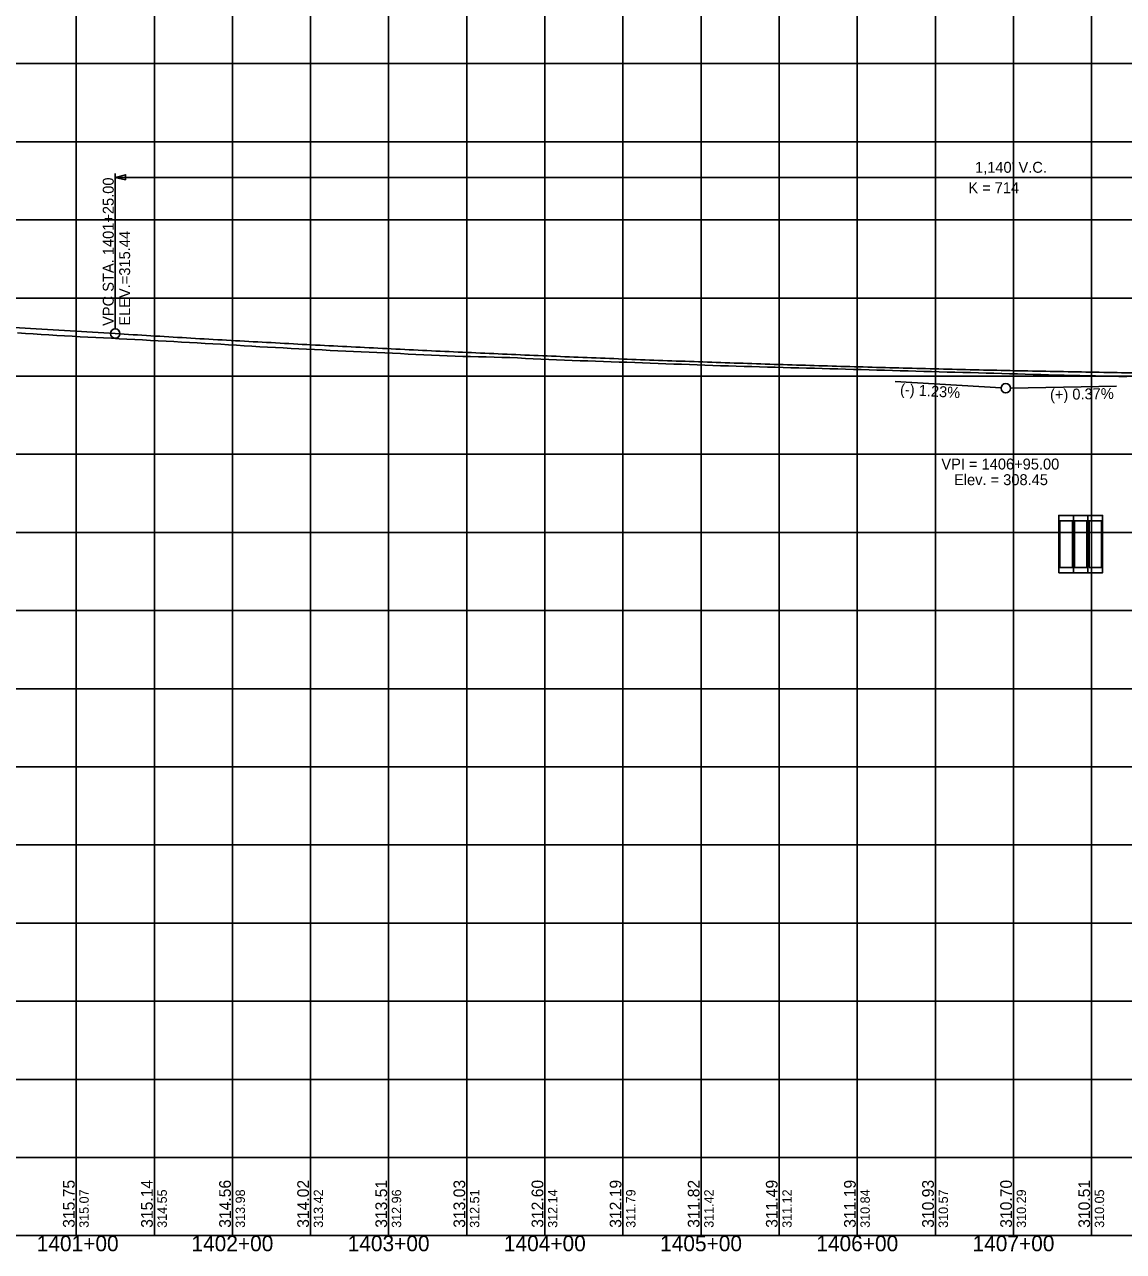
# Model space of a CAD drawing. Extents: x -90830 to 2015517, y -20856 to 836331.
# Drawn here: x 28990 to 29694, y -10807 to -10022 of the extents above; entities that cross this region are included whole.
import ezdxf

# ---------------------------------------------------------------- set-up
doc = ezdxf.new("R2010")
doc.units = 0
for name, color, linetype in [('Level 1', 7, 'Continuous'), ('RD_DDB_GradeTX', 7, 'Continuous'), ('RD_DDB_Profile_Elev', 7, 'Continuous'), ('RD_DDB_Profile_EX', 7, 'Continuous'), ('RD_DDB_Profile_Lbl', 7, 'Continuous'), ('RD_DDB_Profile_PR', 7, 'Continuous'), ('RD_DDB_StaTX', 7, 'Continuous'), ('RD_DDB_StripGrade', 7, 'Continuous'), ('RD_DDB_VCLbl', 7, 'Continuous'), ('RD_EX_DR_Pipe', 7, 'Continuous'), ('RD_GPK_Profile_Cell', 7, 'Continuous'), ('RD_TX_Drainage', 7, 'Continuous')]:
    doc.layers.add(name, color=color, linetype=linetype)

msp = doc.modelspace()

# ---------------------------------------------------------------- linework, layer by layer
at = {"layer": 'Level 1'}
for p, q in [((29023.46, -9797.12), (29023.46, -10297.12)), ((29073.46, -9797.12), (29073.46, -10297.12)), ((29123.46, -9797.12), (29123.46, -10297.12)), ((29173.46, -9797.12), (29173.46, -10297.12)), ((29223.46, -9797.12), (29223.46, -10297.12)), ((29273.46, -9797.12), (29273.46, -10297.12)), ((29323.46, -9797.12), (29323.46, -10297.12)), ((29373.46, -9797.12), (29373.46, -10297.12)), ((29423.46, -9797.12), (29423.46, -10297.12)), ((29473.46, -9797.12), (29473.46, -10297.12)), ((29523.46, -9797.12), (29523.46, -10297.12)), ((29573.46, -9797.12), (29573.46, -10297.12)), ((29623.46, -9797.12), (29623.46, -10297.12)), ((29673.46, -9797.12), (29673.46, -10297.12)), ((28773.46, -10047.12), (30373.46, -10047.12)), ((28773.46, -10097.12), (30373.46, -10097.12)), ((28773.46, -10147.12), (30373.46, -10147.12)), ((28773.46, -10197.12), (30373.46, -10197.12)), ((28773.46, -10247.12), (30373.46, -10247.12)), ((28773.46, -10297.12), (30373.46, -10297.12)), ((28773.46, -10297.12), (30373.46, -10297.12)), ((29023.46, -10297.12), (29023.46, -10797.12)), ((29073.46, -10297.12), (29073.46, -10797.12)), ((29123.46, -10297.12), (29123.46, -10797.12)), ((29173.46, -10297.12), (29173.46, -10797.12)), ((29223.46, -10297.12), (29223.46, -10797.12)), ((29273.46, -10297.12), (29273.46, -10797.12)), ((29323.46, -10297.12), (29323.46, -10797.12)), ((29373.46, -10297.12), (29373.46, -10797.12)), ((29423.46, -10297.12), (29423.46, -10797.12)), ((29473.46, -10297.12), (29473.46, -10797.12)), ((29523.46, -10297.12), (29523.46, -10797.12)), ((29573.46, -10297.12), (29573.46, -10797.12)), ((29623.46, -10297.12), (29623.46, -10797.12)), ((29673.46, -10297.12), (29673.46, -10797.12)), ((28773.46, -10347.12), (30373.46, -10347.12)), ((28773.46, -10397.12), (30373.46, -10397.12)), ((28773.46, -10447.12), (30373.46, -10447.12)), ((28773.46, -10497.12), (30373.46, -10497.12)), ((28773.46, -10547.12), (30373.46, -10547.12)), ((28773.46, -10597.12), (30373.46, -10597.12)), ((28773.46, -10647.12), (30373.46, -10647.12)), ((28773.46, -10697.12), (30373.46, -10697.12)), ((28773.46, -10747.12), (30373.46, -10747.12)), ((28773.46, -10797.12), (30373.46, -10797.12))]:
    msp.add_line(p, q, dxfattribs=at)
at = {"layer": 'RD_DDB_GradeTX'}
for p, q in [((29547.59, -10250.54), (29615.47, -10254.7)), ((29689.45, -10253.57), (29621.46, -10254.83))]:
    msp.add_line(p, q, dxfattribs=at)
msp.add_circle((29618.46, -10254.88), 3, dxfattribs=at)
at = {"layer": 'RD_DDB_Profile_EX'}
for points in [[(28985.95, -10219.49), (28990.95, -10219.81), (28995.95, -10220.13), (29000.95, -10220.45), (29005.95, -10220.77), (29010.95, -10221.04), (29015.95, -10221.32), (29020.95, -10221.6), (29025.95, -10221.88), (29030.95, -10222.13), (29035.95, -10222.37), (29040.95, -10222.62), (29045.95, -10222.87)], [(29045.95, -10222.87), (29050.95, -10223.14), (29055.95, -10223.42), (29060.95, -10223.69), (29065.95, -10223.97), (29070.95, -10224.24), (29075.95, -10224.51), (29080.95, -10224.78), (29085.95, -10225.05), (29090.95, -10225.32), (29095.95, -10225.59), (29100.95, -10225.86), (29105.95, -10226.13), (29110.95, -10226.44), (29115.95, -10226.75), (29120.95, -10227.06), (29125.95, -10227.36), (29130.95, -10227.66), (29135.95, -10227.96), (29140.95, -10228.26), (29145.95, -10228.56), (29150.95, -10228.83), (29155.95, -10229.1), (29160.95, -10229.37), (29165.95, -10229.64), (29170.95, -10229.88), (29175.95, -10230.12), (29180.95, -10230.37), (29185.95, -10230.61), (29190.95, -10230.84), (29195.95, -10231.07), (29200.95, -10231.31), (29205.95, -10231.54), (29210.95, -10231.76), (29215.95, -10231.98), (29220.95, -10232.2), (29225.95, -10232.45), (29230.95, -10232.73), (29235.95, -10233.01), (29240.95, -10233.28), (29245.95, -10233.54), (29250.95, -10233.76), (29255.95, -10233.98), (29260.95, -10234.2), (29265.95, -10234.37), (29270.95, -10234.49), (29275.95, -10234.61), (29280.95, -10234.74), (29285.95, -10234.86), (29290.95, -10234.99), (29295.95, -10235.13), (29300.95, -10235.26), (29305.95, -10235.48), (29310.95, -10235.76), (29315.95, -10236.04), (29320.95, -10236.32), (29325.95, -10236.54), (29330.95, -10236.72), (29335.95, -10236.9), (29340.95, -10237.08), (29345.95, -10237.24), (29350.95, -10237.41), (29355.95, -10237.58), (29360.95, -10237.74), (29365.95, -10237.91), (29370.95, -10238.09), (29375.95, -10238.26), (29380.95, -10238.43), (29385.95, -10238.62), (29390.95, -10238.8), (29395.95, -10238.99), (29400.95, -10239.18), (29405.95, -10239.37), (29410.95, -10239.55), (29415.95, -10239.73), (29420.95, -10239.91), (29425.95, -10240.08), (29430.95, -10240.25), (29435.95, -10240.42), (29440.95, -10240.59), (29445.95, -10240.73), (29450.95, -10240.87), (29455.95, -10241), (29460.95, -10241.14), (29465.95, -10241.28), (29470.95, -10241.43), (29475.95, -10241.57), (29480.95, -10241.71), (29485.95, -10241.85), (29490.95, -10241.98), (29495.95, -10242.11), (29500.95, -10242.24), (29505.95, -10242.39), (29510.95, -10242.53), (29515.95, -10242.68), (29520.95, -10242.83), (29525.95, -10242.97), (29530.95, -10243.11), (29535.95, -10243.25), (29540.95, -10243.4), (29545.95, -10243.53)], [(29545.95, -10243.53), (29550.95, -10243.66), (29555.95, -10243.8), (29560.95, -10243.93), (29565.95, -10244.07), (29570.95, -10244.21), (29575.95, -10244.35), (29580.95, -10244.49), (29585.95, -10244.62), (29590.95, -10244.75), (29595.95, -10244.88), (29600.95, -10245.02), (29605.95, -10245.16), (29610.95, -10245.3), (29615.95, -10245.43), (29620.95, -10245.57), (29625.95, -10245.71), (29630.95, -10245.85), (29635.95, -10246), (29640.95, -10246.13), (29645.95, -10246.26), (29650.95, -10246.39), (29655.95, -10246.52), (29660.95, -10246.65), (29665.95, -10246.74), (29670.95, -10246.84), (29675.95, -10246.94), (29680.95, -10247.05), (29685.95, -10247.16), (29690.95, -10247.28), (29695.95, -10247.39)]]:
    msp.add_lwpolyline(points, dxfattribs=at)
at = {"layer": 'RD_DDB_Profile_PR'}
msp.add_line((28383.46, -10179.13), (29048.46, -10219.92), dxfattribs=at)
msp.add_spline([(29048.46, -10219.92), (29071.26, -10221.3), (29094.06, -10222.65), (29116.86, -10223.95), (29139.66, -10225.22), (29162.46, -10226.46), (29185.26, -10227.66), (29208.06, -10228.82), (29230.86, -10229.94), (29253.66, -10231.03), (29276.46, -10232.09), (29299.26, -10233.1), (29322.06, -10234.08), (29344.86, -10235.03), (29367.66, -10235.93), (29390.46, -10236.8), (29413.26, -10237.64), (29436.06, -10238.43), (29458.86, -10239.2), (29481.66, -10239.92), (29504.46, -10240.61), (29527.26, -10241.26), (29550.06, -10241.88), (29572.86, -10242.46), (29595.66, -10243), (29618.46, -10243.51), (29641.26, -10243.98), (29664.06, -10244.41), (29686.86, -10244.81), (29709.66, -10245.17), (29732.46, -10245.49), (29755.26, -10245.78), (29778.06, -10246.03), (29800.86, -10246.25), (29823.66, -10246.43), (29846.46, -10246.57), (29869.26, -10246.68), (29892.06, -10246.74), (29914.86, -10246.78), (29937.66, -10246.77), (29960.46, -10246.74), (29983.26, -10246.66), (30006.06, -10246.55), (30028.86, -10246.4), (30051.66, -10246.21), (30074.46, -10245.99), (30097.26, -10245.73), (30120.06, -10245.44), (30142.86, -10245.11), (30165.66, -10244.74), (30188.46, -10244.34)], degree=3, dxfattribs=at)
at = {"layer": 'RD_DDB_VCLbl'}
for p, q in [((29048.46, -10117.42), (29048.46, -10216.92)), ((29048.46, -10119.92), (30188.46, -10119.92))]:
    msp.add_line(p, q, dxfattribs=at)
msp.add_circle((29048.46, -10219.92), 3, dxfattribs=at)
at = {"layer": 'RD_EX_DR_Pipe'}
for points in [[(29652.46, -10372.95), (29661.79, -10372.95), (29661.79, -10336.28), (29652.46, -10336.28)], [(29653.13, -10369.62), (29661.13, -10369.62), (29661.13, -10339.62), (29653.13, -10339.62)], [(29661.79, -10372.95), (29671.13, -10372.95), (29671.13, -10336.28), (29661.79, -10336.28)], [(29662.46, -10369.62), (29670.46, -10369.62), (29670.46, -10339.62), (29662.46, -10339.62)], [(29671.13, -10372.95), (29680.46, -10372.95), (29680.46, -10336.28), (29671.13, -10336.28)], [(29671.79, -10369.62), (29679.79, -10369.62), (29679.79, -10339.62), (29671.79, -10339.62)]]:
    msp.add_lwpolyline(points, close=True, dxfattribs=at)
at = {"layer": 'RD_GPK_Profile_Cell'}
msp.add_line((4823.46, -10797.12), (75223.46, -10797.12), dxfattribs=at)
at = {"layer": 'RD_TX_Drainage'}
msp.add_lwpolyline([(29055.06, -10121.57), (29048.46, -10119.92), (29055.06, -10118.27)], close=True, dxfattribs=at)

# ---------------------------------------------------------------- texts
at = {"layer": 'RD_DDB_GradeTX'}
for s, rotation, p in [('(-) 1.23%', 356.49018, (29550.67, -10258.9)), ('(+) 0.37%', 1.05985, (29646.86, -10262.43))]:
    msp.add_text(s, height=7, rotation=rotation, dxfattribs=at).set_placement(p)
at = {"layer": 'RD_DDB_Profile_Elev'}
for s, p in [('315.75', (29022.46, -10792.12)), ('315.14', (29072.46, -10792.12)), ('314.56', (29122.46, -10792.12)), ('314.02', (29172.46, -10792.12)), ('313.51', (29222.46, -10792.12)), ('313.03', (29272.46, -10792.12)), ('312.60', (29322.46, -10792.12)), ('312.19', (29372.46, -10792.12)), ('311.82', (29422.46, -10792.12)), ('311.49', (29472.46, -10792.12)), ('311.19', (29522.46, -10792.12)), ('310.93', (29572.46, -10792.12)), ('310.70', (29622.46, -10792.12)), ('310.51', (29672.46, -10792.12))]:
    msp.add_text(s, height=7.5, rotation=90, dxfattribs=at).set_placement(p)
at = {"layer": 'RD_DDB_Profile_Lbl'}
for s, p in [('VPI = 1406+95.00', (29577.27, -10306.88)), ('Elev. = 308.45', (29585.38, -10316.88))]:
    msp.add_text(s, height=7, dxfattribs=at).set_placement(p)
at = {"layer": 'RD_DDB_StaTX'}
for s, p in [('1401+00', (28998.17, -10807.12)), ('1402+00', (29097.21, -10807.12)), ('1403+00', (29197.21, -10807.12)), ('1404+00', (29297.21, -10807.12)), ('1405+00', (29397.21, -10807.12)), ('1406+00', (29497.21, -10807.12)), ('1407+00', (29597.21, -10807.12))]:
    msp.add_text(s, height=10, dxfattribs=at).set_placement(p)
at = {"layer": 'RD_DDB_StripGrade'}
for s, height, p in [('VPC STA. 1401+25.00 ', 7, (29047.46, -10214.97)), ('ELEV.=315.44', 7, (29057.96, -10214.83)), ('315.07', 6, (29031.46, -10792.12)), ('314.55', 6, (29081.46, -10792.12)), ('313.98', 6, (29131.46, -10792.12)), ('313.42', 6, (29181.46, -10792.12)), ('312.96', 6, (29231.46, -10792.12)), ('312.51', 6, (29281.46, -10792.12)), ('312.14', 6, (29331.46, -10792.12)), ('311.79', 6, (29381.46, -10792.12)), ('311.42', 6, (29431.46, -10792.12)), ('311.12', 6, (29481.46, -10792.12)), ('310.84', 6, (29531.46, -10792.12)), ('310.57', 6, (29581.46, -10792.12)), ('310.29', 6, (29631.46, -10792.12)), ('310.05', 6, (29681.46, -10792.12))]:
    msp.add_text(s, height=height, rotation=90, dxfattribs=at).set_placement(p)
at = {"layer": 'RD_DDB_VCLbl'}
for s, p in [("1,140' V.C.", (29598.83, -10116.98)), ('K = 714', (29594.51, -10130.04))]:
    msp.add_text(s, height=7, dxfattribs=at).set_placement(p)

doc.saveas('drawing.dxf')
